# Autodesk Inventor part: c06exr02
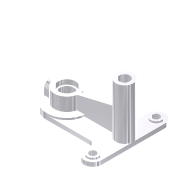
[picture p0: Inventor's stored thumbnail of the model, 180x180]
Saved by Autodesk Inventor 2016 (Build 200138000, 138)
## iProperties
Shininess: 77.0
Length Units: 11269
Angle Units: 11279
Time Units: 11290
Mass Units: 11283
Length Display Precision: 3
Angle Display Precision: 2
Created: 2001-12
Part Number: c06exr02
Document SubType Name: Modeling
Material: Generic
Density: 1 g/cm^3
Appearance: Metal-AL-6061 (Polished)
Density: 0.0
Volumn: 0.0
Area: 0.0
PropertySet Name: Model Information
Control State: 0
Master: False
Checked Out: False
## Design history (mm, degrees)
sketch "Sketch1"
  geometry: L1 (46.121, -53.4)-(46.121, 56.6); L2 (16.121, 56.6)-(16.121, 36.6); L3 (16.121, 36.6)-(-68.879, 36.6); L4 (-68.879, -33.4)-(16.121, -33.4); L5 (16.121, -33.4)-(16.121, -53.4); A1 r 15 centre (31.121, 56.6) between (46.121, 56.6) and (16.121, 56.6); A2 r 35 centre (-68.879, 1.6) between (-68.879, 36.6) and (-68.879, -33.4); A3 r 15 centre (31.121, -53.4) between (16.121, -53.4) and (46.121, -53.4)
  constraints: 10 end point, 6 point on circle, 5 tangent, 3 centre point, 3 parallel, 2 equal length, 1 equal radius, 1 perpendicular, 1 vertical
  dimensions: "d0" = 15 radius of A1; "d1" = 110 distance of L1.start L1.end; "d2" = 100 horizontal distance of A3.centre A2.centre; "d3" = 35 radius of A2
extrude "Extrusion1" new body sketch "Sketch1" distance "d4" = 7; taper "d5" = 0 deg
sketch "Sketch2"
  geometry: C1 r 10 at (31.121, 56.6); C2 r 10 at (31.121, -53.4); C3 r 35 at (-68.879, 1.6); A1 r 35 centre (-68.879, 1.6) between (-68.879, 36.6) and (-68.879, -33.4) reference; A2 r 15 centre (31.121, 56.6) between (46.121, 56.6) and (16.121, 56.6) reference; A3 r 15 centre (31.121, -53.4) between (16.121, -53.4) and (46.121, -53.4) reference
  constraints: 3 centre point, 3 concentric, 2 equal radius
  dimensions: "d45" = 20 diameter of C1
extrude "Extrusion2" join sketch "Sketch2" distance "d6" = 3; taper "d7" = 0 deg
sketch "Sketch3"
  geometry: C1 r 22 at (0, 0); 1 further point
  constraints: 1 centre point, 1 coincident
  dimensions: "d8" = 44 diameter of C1
extrude "Extrusion3" join sketch "Sketch3" distance "d9" = 23; taper "d10" = 0 deg
sketch "Sketch4"
  geometry: L1 (46.121, 56.6)-(46.121, -53.4) reference; L2 (-68.879, 36.6)-(16.121, 36.6) reference; C1 r 15 at (31.121, 1.6)
  constraints: 1 centre point
  dimensions: "d11" = 30 diameter of C1; "d12" = 15 distance from line of L1 C1.centre; "d13" = 35 distance from line of L2 C1.centre
extrude "Extrusion4" join sketch "Sketch4" distance "d14" = 88; taper "d15" = 0 deg
workplane "Work Plane1"
sketch "Sketch5"
  geometry: L1 (22, 33.1)-(85, 48); L2 (0, 7)-(35, 7) reference; L3 (85, 0)-(85, 7) reference; L4 (115, 0)-(115, 7) reference; L5 (115, 0)-(85, 0) reference
  constraints: 2 end point
  dimensions: "d17" = 26.1 distance from line of L2 L1.start; "d18" = 63 distance from line of L3 L1.start; "d19" = 30 distance from line of L4 L1.end; "d20" = 48 distance from line of L5 L1.end
feature "Rib1" sketch "Sketch5" dims "d21" = 1, "d22" = 8
workplane "Work Plane2"
workplane "Work Plane3"
sketch "Sketch7"
  geometry: L1 (10, 0)-(10, 10); L2 (-10, 10)-(-10, 0); L3 (-10, 0)-(10, 0); L4 (55, -10)-(55, -3) reference; A1 r 10 centre (0, 10) between (10, 10) and (-10, 10); 2 further points
  constraints: 6 end point, 2 point on circle, 2 tangent, 1 centre point, 1 parallel, 1 perpendicular, 1 vertical
  dimensions: "d30" = 10 radius of A1; "d34" = 55 distance from line of L4 A1.centre; "d35" = 10 distance of L1.start L1.end
extrude "Extrusion6" join sketch "Sketch7" stored distance "d36" = 88; taper "d37" = 0 deg
sketch "Sketch8"
  geometry: C1 r 10 at (0, 0) reference
hole "Hole1" sketch "Sketch8" at (0, 0) diameter "d38" = 12; stored, may be unused: countersink angle "d42" = 82 deg, drill point angle "d44" = 118 deg; dims "d39" = 6, "d40" = 4, "d41" = 2, "d43" = 8
mirror "Mirror1"
sketch "Sketch9"
  geometry: C1 r 10 at (0, 0)
  constraints: 1 centre point
hole "Hole2" sketch "Sketch9" at (0, 0) diameter "d52" = 18; stored, may be unused: drill point angle "d47" = 118 deg, countersink angle "d48" = 82 deg; dims "d46" = 6, "d49" = 2, "d50" = 4, "d51" = 8
sketch "Sketch10"
  geometry: C1 r 10 at (0, 0)
  constraints: 1 centre point
hole "Hole3" sketch "Sketch10" at (0, 0) diameter "d59" = 24; stored, may be unused: drill point angle "d54" = 118 deg, countersink angle "d55" = 82 deg; dims "d53" = 6, "d56" = 8, "d57" = 30, "d58" = 8
sketch "Sketch11"
  geometry: C1 r 10 at (0, 0)
  constraints: 1 centre point
hole "Hole4" sketch "Sketch11" at (0, 0) diameter "d66" = 10; stored, may be unused: drill point angle "d61" = 0 deg, countersink angle "d62" = 82 deg; dims "d60" = 6, "d63" = 2, "d64" = 4, "d65" = 8
fillet "Fillet1" dims "d67" = 10
body "Solid1"
other parameters: "d16" = -35, "d29" = -8
